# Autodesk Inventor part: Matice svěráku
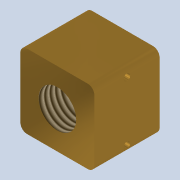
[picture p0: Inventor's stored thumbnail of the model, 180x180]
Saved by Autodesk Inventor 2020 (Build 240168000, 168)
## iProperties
Created: 2025-03
Part Number: Matice svěráku
Material: Mosaz, měkká žlutá
Document SubType Name: Modeling
Designer: doma
Density: 8.47 g/cm^3
Appearance: Mosaz – satén
Mass: 229.214 g
Surface Area: 75.8196 cm^2
Volume: 27.0619 cm^3
Author: doma
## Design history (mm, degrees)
sketch "Náčrt1"
  geometry: L1 (-17, -17)-(17, -17); L2 (17, -17)-(17, 17); L3 (17, 17)-(-17, 17); L4 (-17, 17)-(-17, -17); L5 (-17, -17)-(17, 17); L6 (17, -17)-(-17, 17); 1 further point
  constraints: 12 end point, 2 midpoint, 2 parallel, 1 horizontal, 1 perpendicular
  dimensions: "d0" = 34 distance of L3.end L2.end; "d1" = 34 distance of L2.end L1.end
extrude "Vysunutí1" new body sketch "Náčrt1" distance "d2" = 30; taper "d3" = 0 deg
fillet "Zaoblení1" dims "d4" = 3
sketch "Náčrt2"
  geometry: 2 further points
  constraints: 1 coincident
hole "Díra1" sketch "Náčrt2" at (0, 0) diameter "d5" = 17.294; stored, may be unused: countersink angle "d9" = 90 deg, drill point angle "d11" = 118 deg; dims "d6" = 40, "d7" = 4, "d8" = 2, "d10" = 51.2
sketch "Náčrt4"
  geometry: L1 (0, -3)-(30, -3) reference; L2 (30, 31)-(0, 31) reference; 3 further points
  dimensions: "d22" = 4 distance from line of L1 point (15, 1); "d23" = 4 distance from line of L2 point (15, 27) (= d22)
hole "Díra3" sketch "Náčrt4" at (15, 1), (15, 27) diameter "d24" = 3; stored, may be unused: countersink angle "d28" = 90 deg, drill point angle "d30" = 118 deg; dims "d25" = 6, "d26" = 4, "d27" = 2, "d29" = 8
node "Těleso1"
